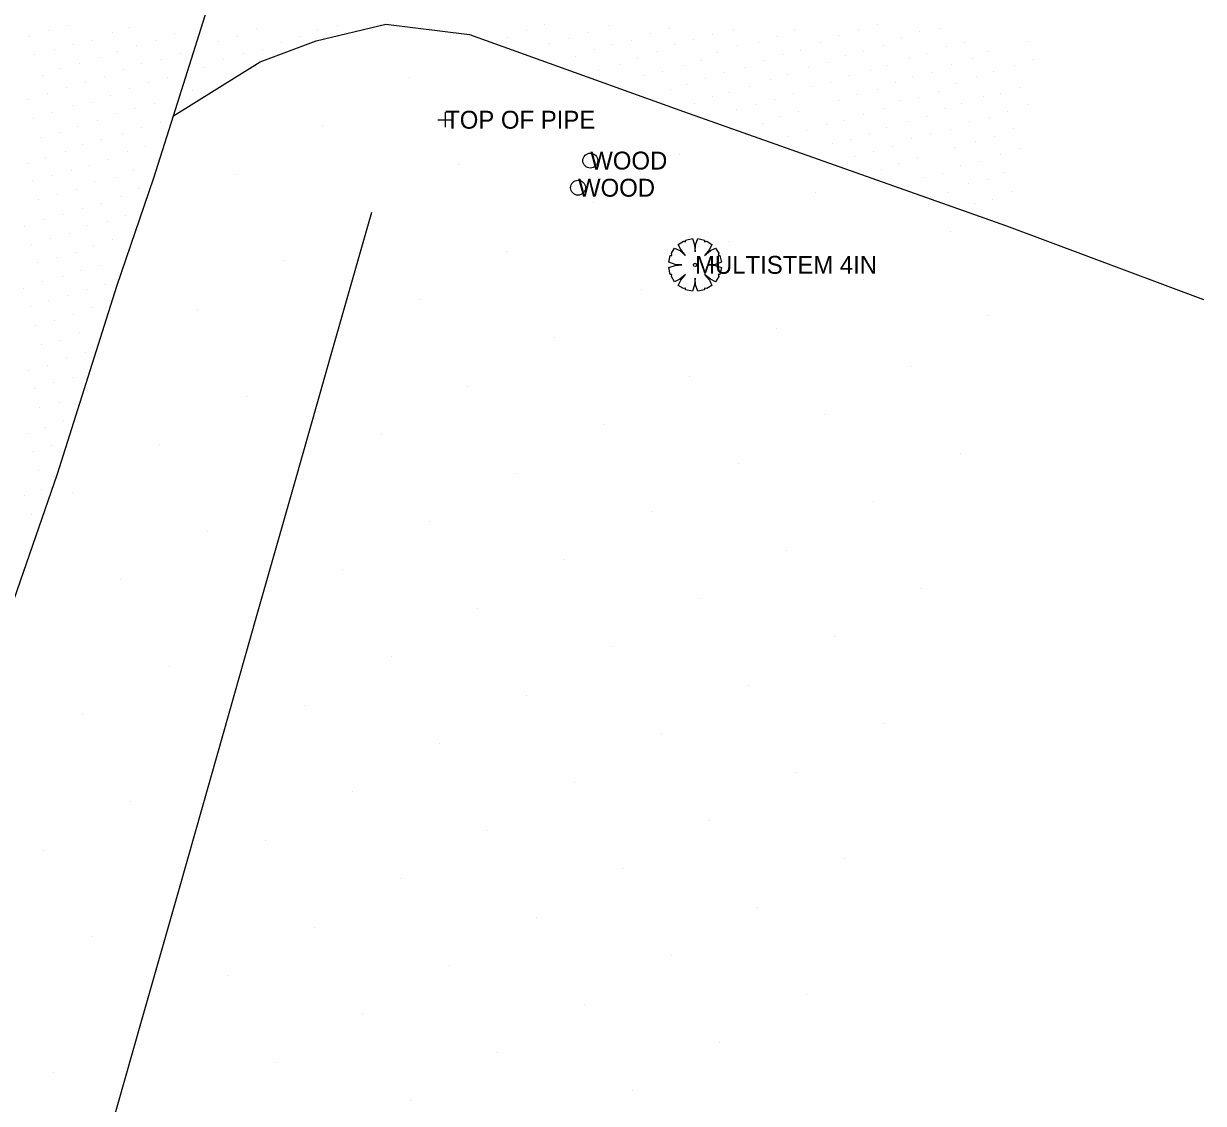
# Model space of a CAD drawing. Extents: x 1733582 to 1734070, y 467256 to 468256.
# Drawn here: x 1733925.7 to 1734044.5, y 467910.6 to 468019.2 of the extents above; entities that cross this region are included whole.
import ezdxf

# ---------------------------------------------------------------- set-up
doc = ezdxf.new("R2010")
doc.units = 0
for name, color, linetype in [('Default', 7, 'Continuous'), ('S_Drainage_Invert_Culvert', 7, 'Continuous'), ('S_Ground_LevelString', 7, 'Continuous'), ('S_Ground_SpotElevation', 7, 'Continuous'), ('S_Roadway_Drive_Paved', 7, 'Continuous'), ('S_Roadway_Edge_Pavement', 7, 'Continuous'), ('S_Text', 7, 'Continuous'), ('S_Traffic_Posts', 7, 'Continuous'), ('S_Trees_Decid_NonPay', 7, 'Continuous')]:
    doc.layers.add(name, color=color, linetype=linetype)

# ---------------------------------------------------------------- blocks, each defined once
blk = doc.blocks.new('POINT_DISPLAY')
at = {"layer": 'Default'}
blk.add_line((0, 0), (0, 0), dxfattribs=at)

msp = doc.modelspace()

# ---------------------------------------------------------------- linework, layer by layer
at = {"layer": 'S_Drainage_Invert_Culvert'}
for p, q in [((1733968.18, 468010.3), (1733968.18, 468008.8)), ((1733967.43, 468009.55), (1733968.93, 468009.55))]:
    msp.add_line(p, q, dxfattribs=at)
at = {"layer": 'S_Ground_LevelString'}
msp.add_lwpolyline([(1733960.75, 468000.21), (1733956.87, 467986.61), (1733953, 467973.01), (1733949.13, 467959.4), (1733945.26, 467945.8), (1733941.39, 467932.2), (1733937.52, 467918.6), (1733933.64, 467905), (1733929.77, 467891.4), (1733925.9, 467877.79)], dxfattribs=at)
at = {"layer": 'S_Roadway_Drive_Paved'}
msp.add_lwpolyline([(1733940.84, 468009.95), (1733949.55, 468015.38), (1733955.2, 468017.5), (1733962.22, 468019.16), (1733970.63, 468018.11), (1733992.17, 468010.37), (1734024.68, 467998.86), (1734044.52, 467991.47)], dxfattribs=at)
at = {"layer": 'S_Roadway_Edge_Pavement'}
for points in [[(1733940.84, 468009.95), (1733945.03, 468023.26), (1733950.45, 468039.97), (1733955.3, 468055.37), (1733958.83, 468065.66)], [(1733886.81, 467847.75), (1733888.65, 467853.28), (1733891.75, 467863.74), (1733894.08, 467872.4), (1733897, 467882.03), (1733899.76, 467891.08), (1733902.19, 467897.23), (1733906.27, 467907.96), (1733909.56, 467915.95), (1733911.21, 467921.13), (1733913.6, 467927.78), (1733917.17, 467937.65), (1733920.6, 467948.44), (1733924.18, 467959.58), (1733929.14, 467973.94), (1733935.13, 467992.82), (1733938.85, 468003.7), (1733940.84, 468009.95)]]:
    msp.add_lwpolyline(points, dxfattribs=at)
at = {"layer": 'S_Traffic_Posts'}
for centre in [(1733982.79, 468005.44), (1733981.56, 468002.71)]:
    msp.add_circle(centre, 0.749, dxfattribs=at)
at = {"layer": 'S_Trees_Decid_NonPay'}
msp.add_lwpolyline([(1733992.02, 467994.95), (1733991.33, 467995), (1733990.69, 467995.21), (1733990.85, 467995.9), (1733991.01, 467995.9), (1733990.96, 467996.11), (1733991.28, 467996.64), (1733991.81, 467996.38), (1733992.39, 467995.9), (1733991.91, 467996.48), (1733991.65, 467997.01), (1733992.18, 467997.33), (1733992.39, 467997.28), (1733992.39, 467997.44), (1733993.08, 467997.6), (1733993.29, 467996.96), (1733993.35, 467996.27), (1733993.4, 467996.96), (1733993.61, 467997.6), (1733994.3, 467997.44), (1733994.3, 467997.28), (1733994.51, 467997.33), (1733995.04, 467997.01), (1733994.78, 467996.48), (1733994.3, 467995.9), (1733994.88, 467996.38), (1733995.41, 467996.64), (1733995.73, 467996.11), (1733995.68, 467995.9), (1733995.84, 467995.9), (1733996, 467995.21), (1733995.36, 467995), (1733994.67, 467994.95), (1733995.36, 467994.89), (1733996, 467994.68), (1733995.84, 467993.99), (1733995.68, 467993.99), (1733995.73, 467993.78), (1733995.41, 467993.25), (1733994.88, 467993.51), (1733994.3, 467993.99), (1733994.78, 467993.41), (1733995.04, 467992.88), (1733994.51, 467992.56), (1733994.3, 467992.61), (1733994.3, 467992.45), (1733993.61, 467992.29), (1733993.4, 467992.93), (1733993.35, 467993.62), (1733993.29, 467992.93), (1733993.08, 467992.29), (1733992.39, 467992.45), (1733992.39, 467992.61), (1733992.18, 467992.56), (1733991.65, 467992.88), (1733991.91, 467993.41), (1733992.39, 467993.99), (1733991.81, 467993.51), (1733991.28, 467993.25), (1733990.96, 467993.78), (1733991.01, 467993.99), (1733990.85, 467993.99), (1733990.69, 467994.68), (1733991.33, 467994.89), (1733992.02, 467994.95)], dxfattribs=at)
msp.add_circle((1733993.34, 467994.95), 0.166, dxfattribs=at)

# ---------------------------------------------------------------- block references
at = {"layer": 'S_Ground_SpotElevation'}
for p in [(1733978.16, 468019.16), (1734011.73, 468019.08), (1733926.31, 468017.9), (1733928.26, 468018.55), (1733930.17, 468019.02), (1733934.65, 468018.28), (1733936.44, 468018.86), (1733940.95, 468018.27), (1733947.27, 468017.94), (1733949.15, 468018.75), (1733953.48, 468017.97), (1733955.35, 468018.6), (1733957.34, 468019.07), (1733976.35, 468018.53), (1733982.58, 468018.31), (1733984.58, 468019.06), (1733988.9, 468018.27), (1733990.8, 468018.69), (1733995.06, 468018.11), (1733997.24, 468018.67), (1734003.35, 468018.63), (1734007.8, 468018.03), (1734009.82, 468018.61), (1734015.95, 468018.39), (1734017.98, 468018.71), (1733930.76, 468017.12), (1733932.66, 468017.57), (1733937.14, 468017.05), (1733939.04, 468017.53), (1733945.4, 468017.38), (1733951.71, 468017.29), (1733974.46, 468017.87), (1733978.72, 468017.19), (1733980.64, 468017.73), (1733985.04, 468017.13), (1733986.9, 468017.53), (1733991.3, 468017.14), (1733993.18, 468017.63), (1733997.65, 468016.98), (1733999.74, 468017.27), (1734001.64, 468017.89), (1734006.01, 468017.36), (1734012.32, 468017.03), (1734014.11, 468017.79), (1734018.66, 468016.93), (1734020.47, 468017.36), (1734026.91, 468017.4), (1733926.86, 468016.08), (1733928.89, 468016.61), (1733933.35, 468015.79), (1733935.21, 468016.41), (1733939.65, 468015.63), (1733941.55, 468016.22), (1733945.89, 468015.59), (1733947.87, 468016.18), (1733949.8, 468016.61), (1733981.27, 468015.96), (1733983.26, 468016.61), (1733987.54, 468015.73), (1733989.54, 468016.42), (1733993.99, 468015.54), (1733995.62, 468016.29), (1734000.25, 468015.53), (1734002.24, 468016.13), (1734003.94, 468016.56), (1734008.45, 468015.99), (1734010.27, 468016.4), (1734014.95, 468015.71), (1734016.63, 468016.21), (1734021.26, 468015.68), (1734022.9, 468016.37), (1734027.38, 468015.65), (1733929.45, 468014.73), (1733931.32, 468015.24), (1733935.75, 468014.6), (1733937.6, 468015.25), (1733943.97, 468014.8), (1733983.6, 468014.54), (1733985.8, 468015.09), (1733990.03, 468014.37), (1733992.16, 468014.99), (1733998.43, 468014.81), (1734004.8, 468014.82), (1734006.72, 468015.34), (1734011, 468014.54), (1734012.7, 468015.05), (1734019.14, 468015.11), (1734023.43, 468014.41), (1734025.45, 468014.98), (1733927.61, 468014.03), (1733931.93, 468013.3), (1733933.88, 468013.94), (1733938.29, 468013.25), (1733940.24, 468013.78), (1733964.62, 468013.81), (1733988.19, 468013.96), (1733994.36, 468013.68), (1733996.3, 468014.3), (1734000.98, 468013.58), (1734002.61, 468014.06), (1734007.02, 468013.27), (1734008.93, 468014.04), (1734013.51, 468013.31), (1734015.23, 468013.88), (1734017.22, 468014.29), (1734019.6, 468013.17), (1734021.66, 468013.87), (1733928.19, 468012.16), (1733930.1, 468012.79), (1733934.5, 468011.99), (1733936.37, 468012.71), (1733942.71, 468012.49), (1733990.83, 468012.6), (1733992.45, 468013.1), (1733996.83, 468012.32), (1733998.8, 468012.92), (1734003.21, 468012.22), (1734005.16, 468012.93), (1734009.63, 468012.06), (1734011.67, 468012.6), (1734017.85, 468012.38), (1734024.11, 468012.21), (1734026.03, 468012.79), (1733926.26, 468011.59), (1733930.63, 468010.96), (1733932.6, 468011.33), (1733938.91, 468011.18), (1733993.3, 468011.23), (1733995.12, 468011.85), (1733999.4, 468011.12), (1734001.29, 468011.54), (1734007.81, 468011.5), (1734013.98, 468011.47), (1734015.85, 468011.82), (1734020.17, 468011.15), (1734022.36, 468011.91), (1734026.82, 468011.13), (1733926.7, 468009.68), (1733928.7, 468010.32), (1733935.01, 468010.16), (1733936.88, 468010.68), (1733978.22, 468009.94), (1733997.56, 468010.53), (1734001.98, 468009.84), (1734003.73, 468010.35), (1734010.27, 468010.08), (1734012.27, 468010.72), (1734016.65, 468009.91), (1734018.57, 468010.71), (1734022.99, 468009.79), (1734024.79, 468010.35), (1733931.21, 468008.88), (1733933.16, 468009.45), (1733937.59, 468008.81), (1733939.51, 468009.3), (1733955.88, 468008.95), (1734000.08, 468009.15), (1734004.59, 468008.43), (1734006.57, 468009.06), (1734008.42, 468009.52), (1734012.65, 468008.75), (1734014.73, 468009.41), (1734019.06, 468008.54), (1734020.95, 468009.39), (1734025.43, 468008.62), (1733927.44, 468007.81), (1733929.38, 468008.29), (1733933.58, 468007.54), (1733935.67, 468008.18), (1734002.65, 468007.84), (1734008.96, 468007.61), (1734010.92, 468008.16), (1734015.17, 468007.66), (1734017.07, 468008.13), (1734021.55, 468007.33), (1734023.48, 468007.86), (1733929.93, 468006.39), (1733931.7, 468007.05), (1733936.25, 468006.31), (1733938.06, 468006.89), (1733991.82, 468006.07), (1734007.14, 468007.12), (1734011.29, 468006.38), (1734013.2, 468006.9), (1734019.47, 468006.78), (1734026.02, 468006.64), (1733926.09, 468005.15), (1733927.94, 468005.79), (1733932.41, 468004.97), (1733934.32, 468005.53), (1733969.48, 468005.07), (1734009.39, 468005.85), (1734013.84, 468005.18), (1734015.69, 468005.7), (1734020.09, 468004.91), (1734021.99, 468005.32), (1734024.04, 468006.01), (1733928.55, 468003.9), (1733930.54, 468004.42), (1733934.95, 468003.75), (1733936.82, 468004.47), (1733947.14, 468004.08), (1734012.12, 468004.54), (1734016.3, 468003.75), (1734018.23, 468004.11), (1734024.52, 468004.21), (1733926.67, 468003.46), (1733931.1, 468002.54), (1733932.93, 468003.31), (1733937.31, 468002.61), (1734020.89, 468003.1), (1734022.85, 468003.52), (1733927.28, 468001.48), (1733929.16, 468002), (1733935.55, 468001.85), (1734005.42, 468002.2), (1734018.83, 468002.26), (1734023.3, 468001.54), (1734025.33, 468002.32), (1733931.69, 468000.64), (1733933.59, 468001.13), (1733960.75, 468000.21), (1733983.08, 468001.2), (1734021.49, 468001.08), (1733927.87, 467999.51), (1733929.77, 468000.05), (1733934.22, 467999.3), (1733936.03, 467999.93), (1733925.86, 467998.77), (1733930.35, 467998.09), (1733932.16, 467998.88), (1734019.02, 467998.32), (1733926.58, 467996.96), (1733928.44, 467997.61), (1733932.77, 467996.85), (1733934.74, 467997.53), (1733996.69, 467997.33), (1733929.05, 467995.66), (1733930.96, 467996.21), (1733952.01, 467995.34), (1733974.35, 467996.34), (1733927.15, 467995.14), (1733931.52, 467994.38), (1733933.46, 467994.87), (1733927.67, 467993.32), (1733929.61, 467993.78), (1733933.97, 467993), (1734010.29, 467993.46), (1733925.75, 467992.54), (1733930.23, 467991.87), (1733932.13, 467992.43), (1733987.95, 467992.47), (1733926.41, 467990.76), (1733928.28, 467991.39), (1733932.68, 467990.65), (1733965.61, 467991.47), (1733930.76, 467989.99), (1733943.27, 467990.48), (1734022.92, 467989.85), (1733926.98, 467988.82), (1733928.88, 467989.37), (1734001.55, 467988.59), (1733929.45, 467987.34), (1733931.39, 467988.1), (1733979.21, 467987.6), (1733927.54, 467986.9), (1733931.95, 467986.14), (1733956.87, 467986.61), (1733928.1, 467984.83), (1733930.04, 467985.63), (1734015.15, 467984.72), (1733926.22, 467984.35), (1733930.63, 467983.64), (1733992.81, 467983.73), (1733926.83, 467982.54), (1733928.71, 467983.12), (1733970.48, 467982.74), (1733948.14, 467981.74), (1733927.39, 467980.58), (1733929.35, 467981.07), (1733929.72, 467979.29), (1733984.08, 467978.86), (1734006.42, 467979.86), (1733926.09, 467978.03), (1733927.96, 467978.6), (1733961.74, 467977.87), (1733928.6, 467976.77), (1733939.4, 467976.88), (1733926.69, 467976.15), (1734020.02, 467975.99), (1733927.24, 467974.25), (1733975.34, 467974), (1733997.68, 467974.99), (1733953, 467973.01), (1733925.88, 467971.71), (1733927.52, 467972.32), (1733930.66, 467972.01), (1734011.28, 467971.12), (1733926.53, 467969.86), (1733988.94, 467970.13), (1733944.27, 467968.14), (1733966.6, 467969.13), (1734002.54, 467966.26), (1733980.21, 467965.26), (1733935.53, 467963.28), (1733957.87, 467964.27), (1734016.15, 467962.38), (1733993.81, 467961.39), (1733971.47, 467960.4), (1733949.13, 467959.4), (1734007.41, 467957.52), (1733985.07, 467956.53), (1733962.73, 467955.53), (1733940.39, 467954.54), (1733998.67, 467952.65), (1733976.33, 467951.66), (1733954, 467950.67), (1733931.66, 467949.67), (1734012.27, 467948.78), (1733967.6, 467946.8), (1733989.94, 467947.79), (1733945.26, 467945.8), (1734003.54, 467943.92), (1733958.86, 467941.93), (1733981.2, 467942.92), (1733936.52, 467940.94), (1733994.8, 467939.05), (1733972.46, 467938.06), (1733927.79, 467936.07), (1733950.12, 467937.07), (1734008.4, 467935.18), (1733986.06, 467934.19), (1733963.73, 467933.19), (1733941.39, 467932.2), (1733999.67, 467930.32), (1733977.33, 467929.32), (1733954.99, 467928.33), (1733932.65, 467927.34), (1733990.93, 467925.45), (1733968.59, 467924.46), (1733946.25, 467923.46), (1733982.19, 467920.59), (1734004.53, 467921.58), (1733959.85, 467919.59), (1733937.52, 467918.6), (1733995.79, 467916.71), (1733951.12, 467914.73), (1733973.46, 467915.72), (1733928.78, 467913.73), (1733987.06, 467911.85), (1733964.72, 467910.86)]:
    msp.add_blockref('POINT_DISPLAY', p, dxfattribs=at)

# ---------------------------------------------------------------- texts
at = {"layer": 'S_Text'}
for s, p in [('TOP OF PIPE', (1733968.18, 468008.65)), ('WOOD', (1733982.79, 468004.54)), ('WOOD', (1733981.56, 468001.81)), ('MULTISTEM 4IN', (1733993.34, 467994.05))]:
    msp.add_text(s, height=1.8, dxfattribs=at).set_placement(p)

doc.saveas('drawing.dxf')
